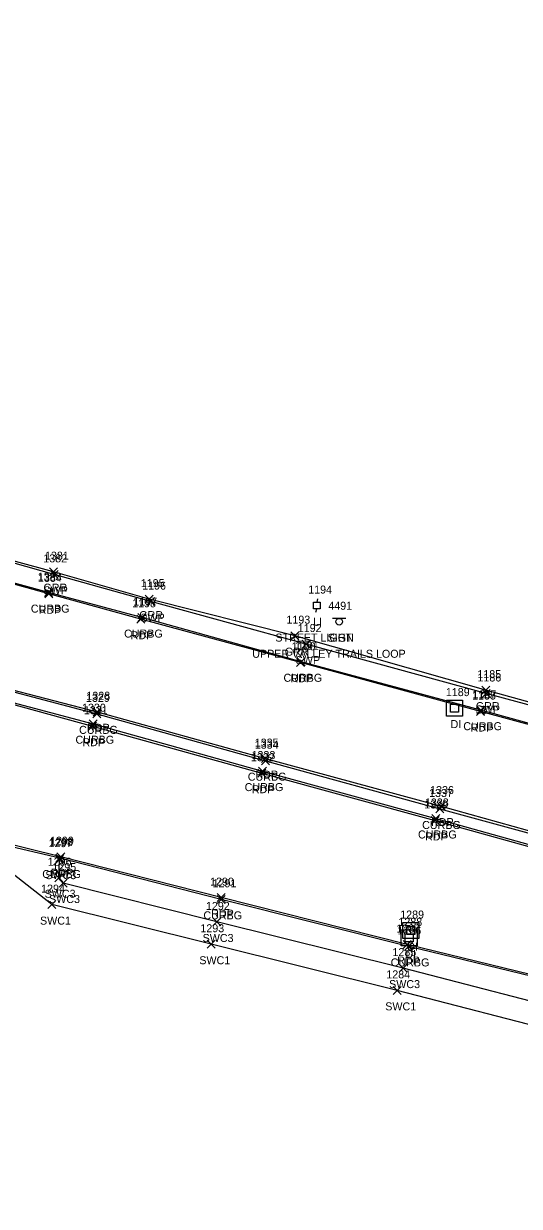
# Model space of a CAD drawing. Extents: x 1690689 to 1696275, y 438760 to 444007.
# Drawn here: x 1692829.1 to 1692953, y 438782.1 to 439077.7 of the extents above; entities that cross this region are included whole.
import ezdxf

# ---------------------------------------------------------------- set-up
doc = ezdxf.new("R2010")
doc.units = 0
for name, color, linetype in [('D_A', 7, 'Continuous'), ('D_I', 7, 'Continuous'), ('DS', 7, 'Continuous'), ('P_A', 7, 'Continuous'), ('P_I', 7, 'Continuous'), ('P_TIC', 7, 'Continuous'), ('PET', 7, 'Continuous'), ('R_A', 7, 'Continuous'), ('R_I', 7, 'Continuous'), ('R_TIC', 7, 'Continuous'), ('RC', 7, 'Continuous'), ('RGR', 7, 'Continuous'), ('RSW', 7, 'Continuous'), ('S_A', 7, 'Continuous'), ('S_C', 7, 'Continuous'), ('S_I', 7, 'Continuous'), ('SSGN', 7, 'Continuous'), ('U_A', 7, 'Continuous'), ('U_C', 7, 'Continuous'), ('U_I', 7, 'Continuous'), ('ULP', 7, 'Continuous')]:
    doc.layers.add(name, color=color, linetype=linetype)

msp = doc.modelspace()

# ---------------------------------------------------------------- linework, layer by layer
at = {"layer": 'DS'}
for p, q in [((1692934.77, 438908.65), (1692938.77, 438908.65)), ((1692934.77, 438904.65), (1692934.77, 438908.65)), ((1692935.77, 438905.65), (1692935.77, 438907.65)), ((1692935.77, 438907.65), (1692937.77, 438907.65)), ((1692937.77, 438907.65), (1692937.77, 438905.65)), ((1692938.77, 438908.65), (1692938.77, 438904.65)), ((1692937.77, 438905.65), (1692935.77, 438905.65)), ((1692936.77, 438906.65), (1692936.77, 438906.65)), ((1692936.77, 438906.65), (1692936.77, 438906.65)), ((1692938.77, 438904.65), (1692934.77, 438904.65)), ((1692923.93, 438853.06), (1692927.93, 438853.06)), ((1692923.93, 438849.06), (1692923.93, 438853.06)), ((1692924.93, 438850.06), (1692924.93, 438852.06)), ((1692924.93, 438852.06), (1692926.93, 438852.06)), ((1692926.93, 438852.06), (1692926.93, 438850.06)), ((1692927.93, 438853.06), (1692927.93, 438849.06)), ((1692923.47, 438851.22), (1692927.47, 438851.22)), ((1692923.47, 438847.22), (1692923.47, 438851.22)), ((1692927.93, 438849.06), (1692923.93, 438849.06)), ((1692924.47, 438848.22), (1692924.47, 438850.22)), ((1692924.47, 438850.22), (1692926.47, 438850.22)), ((1692926.93, 438850.06), (1692924.93, 438850.06)), ((1692925.47, 438849.22), (1692925.47, 438849.22)), ((1692925.47, 438849.22), (1692925.47, 438849.22)), ((1692925.94, 438851.06), (1692925.94, 438851.06)), ((1692925.94, 438851.06), (1692925.94, 438851.06)), ((1692926.47, 438850.22), (1692926.47, 438848.22)), ((1692927.47, 438851.22), (1692927.47, 438847.22)), ((1692927.47, 438847.22), (1692923.47, 438847.22)), ((1692926.47, 438848.22), (1692924.47, 438848.22))]:
    msp.add_line(p, q, dxfattribs=at)
at = {"layer": 'P_TIC'}
for points in [[(1692834.39, 438934.21), (1692836.39, 438936.21)], [(1692836.39, 438934.21), (1692834.39, 438936.21)], [(1692857.37, 438927.85), (1692859.37, 438929.85)], [(1692859.37, 438927.85), (1692857.37, 438929.85)], [(1692897.33, 438917.08), (1692899.33, 438919.08)], [(1692899.33, 438917.08), (1692897.33, 438919.08)], [(1692846.49, 438904.73), (1692848.49, 438906.73)], [(1692848.49, 438904.73), (1692846.49, 438906.73)], [(1692942.33, 438904.8), (1692944.33, 438906.8)], [(1692944.33, 438904.8), (1692942.33, 438906.8)], [(1692845.3, 438901.13), (1692847.3, 438903.13)], [(1692847.3, 438901.13), (1692845.3, 438903.13)], [(1692888.57, 438893.03), (1692890.57, 438895.03)], [(1692890.57, 438893.03), (1692888.57, 438895.03)], [(1692887.63, 438889.39), (1692889.63, 438891.39)], [(1692889.63, 438889.39), (1692887.63, 438891.39)], [(1692932.46, 438881.17), (1692934.46, 438883.17)], [(1692934.46, 438881.17), (1692932.46, 438883.17)], [(1692930.95, 438877.57), (1692932.95, 438879.57)], [(1692932.95, 438877.57), (1692930.95, 438879.57)], [(1692837.41, 438868.51), (1692839.41, 438870.51)], [(1692839.41, 438868.51), (1692837.41, 438870.51)], [(1692877.5, 438858.29), (1692879.5, 438860.29)], [(1692879.5, 438858.29), (1692877.5, 438860.29)], [(1692923.99, 438846.57), (1692925.99, 438848.57)], [(1692925.99, 438846.57), (1692923.99, 438848.57)]]:
    msp.add_lwpolyline(points, dxfattribs=at)
at = {"layer": 'PET'}
for points in [[(1693125.8, 439077.7), (1693116.74, 439032.37), (1693117.43, 439025.65), (1693115.9, 439015.71), (1693111.21, 439002.42), (1693106.01, 438991.1), (1693085.1, 438953.79), (1693072.88, 438932.02), (1693062.34, 438914.66), (1693048.8, 438898.45), (1693044.46, 438895.45), (1693034.2, 438890.8), (1693027.9, 438888.88), (1693020.98, 438887.4), (1693013.55, 438887.23), (1693007.21, 438888.24), (1692984.73, 438894.57), (1692943.33, 438905.8), (1692898.33, 438918.08), (1692858.37, 438928.85), (1692835.39, 438935.21), (1692797.06, 438945.81)], [(1693167.67, 438782.57), (1693141.53, 438790.2), (1693112.15, 438798.3), (1693087.86, 438805.04), (1693057.06, 438813.51), (1693019.12, 438823.55), (1692973.09, 438835.84), (1692924.99, 438847.57), (1692878.5, 438859.29), (1692838.41, 438869.51), (1692796.94, 438879.76), (1692752.35, 438890.07), (1692731.67, 438894.52), (1692658.1, 438910.21), (1692638.65, 438914.4), (1692605.27, 438921.45), (1692561.1, 438930.73), (1692527.61, 438937.28), (1692485.07, 438945.57), (1692435.03, 438955.4)], [(1692767.64, 438925.55), (1692788.12, 438920.87), (1692810.81, 438915.2), (1692847.49, 438905.73), (1692889.57, 438894.03), (1692933.46, 438882.17), (1692980.03, 438869.15), (1693015.23, 438859.21), (1693027.67, 438855.11), (1693029.13, 438853.87), (1693029.26, 438853.13)], [(1692765.95, 438921.86), (1692787.57, 438917.51), (1692810.13, 438912.04), (1692846.3, 438902.13), (1692888.63, 438890.39), (1692931.95, 438878.57), (1692979.05, 438865.49), (1693014.1, 438855.52), (1693026.61, 438851.49), (1693027.81, 438851.47), (1693028.79, 438852.15), (1693029.26, 438853.13)]]:
    msp.add_lwpolyline(points, dxfattribs=at)
at = {"layer": 'R_TIC'}
for points in [[(1692835.58, 438939.74), (1692837.58, 438941.74)], [(1692837.58, 438939.74), (1692835.58, 438941.74)], [(1692835.71, 438939.07), (1692837.71, 438941.07)], [(1692837.71, 438939.07), (1692835.71, 438941.07)], [(1692834.33, 438934.51), (1692836.33, 438936.51)], [(1692836.33, 438934.51), (1692834.33, 438936.51)], [(1692859.53, 438932.88), (1692861.53, 438934.88)], [(1692861.53, 438932.88), (1692859.53, 438934.88)], [(1692859.92, 438932.26), (1692861.92, 438934.26)], [(1692861.92, 438932.26), (1692859.92, 438934.26)], [(1692857.65, 438928.27), (1692859.65, 438930.27)], [(1692859.65, 438928.27), (1692857.65, 438930.27)], [(1692895.92, 438923.75), (1692897.92, 438925.75)], [(1692897.92, 438923.75), (1692895.92, 438925.75)], [(1692898.76, 438921.66), (1692900.76, 438923.66)], [(1692900.76, 438921.66), (1692898.76, 438923.66)], [(1692897.49, 438917.23), (1692899.49, 438919.23)], [(1692899.49, 438917.23), (1692897.49, 438919.23)], [(1692943.65, 438910.14), (1692945.65, 438912.14)], [(1692945.65, 438910.14), (1692943.65, 438912.14)], [(1692943.72, 438909.3), (1692945.72, 438911.3)], [(1692945.72, 438909.3), (1692943.72, 438911.3)], [(1692846.4, 438904.21), (1692848.4, 438906.21)], [(1692848.4, 438904.21), (1692846.4, 438906.21)], [(1692942.42, 438905.13), (1692944.42, 438907.13)], [(1692944.42, 438905.13), (1692942.42, 438907.13)], [(1692845.5, 438901.75), (1692847.5, 438903.75)], [(1692847.5, 438901.75), (1692845.5, 438903.75)], [(1692888.57, 438892.51), (1692890.57, 438894.51)], [(1692890.57, 438892.51), (1692888.57, 438894.51)], [(1692887.78, 438889.91), (1692889.78, 438891.91)], [(1692889.78, 438889.91), (1692887.78, 438891.91)], [(1692932.14, 438880.44), (1692934.14, 438882.44)], [(1692934.14, 438880.44), (1692932.14, 438882.44)], [(1692931.11, 438878.07), (1692933.11, 438880.07)], [(1692933.11, 438878.07), (1692931.11, 438880.07)], [(1692837.06, 438867.91), (1692839.06, 438869.91)], [(1692839.06, 438867.91), (1692837.06, 438869.91)], [(1692837.19, 438868.18), (1692839.19, 438870.18)], [(1692839.19, 438868.18), (1692837.19, 438870.18)], [(1692836.89, 438863.26), (1692838.89, 438865.26)], [(1692838.89, 438863.26), (1692836.89, 438865.26)], [(1692838, 438861.94), (1692840, 438863.94)], [(1692840, 438861.94), (1692838, 438863.94)], [(1692835.17, 438856.54), (1692837.17, 438858.54)], [(1692837.17, 438856.54), (1692835.17, 438858.54)], [(1692877.46, 438857.86), (1692879.46, 438859.86)], [(1692879.46, 438857.86), (1692877.46, 438859.86)], [(1692876.37, 438852.2), (1692878.37, 438854.2)], [(1692878.37, 438852.2), (1692876.37, 438854.2)], [(1692874.99, 438846.64), (1692876.99, 438848.64)], [(1692876.99, 438846.64), (1692874.99, 438848.64)], [(1692924.29, 438846.1), (1692926.29, 438848.1)], [(1692926.29, 438846.1), (1692924.29, 438848.1)], [(1692922.99, 438840.68), (1692924.99, 438842.68)], [(1692924.99, 438840.68), (1692922.99, 438842.68)], [(1692921.46, 438835.11), (1692923.46, 438837.11)], [(1692923.46, 438835.11), (1692921.46, 438837.11)]]:
    msp.add_lwpolyline(points, dxfattribs=at)
at = {"layer": 'RC'}
for points in [[(1693007.26, 438888.54), (1692984.87, 438894.72), (1692943.42, 438906.13), (1692898.49, 438918.23), (1692858.65, 438929.27), (1692835.33, 438935.51), (1692797.49, 438945.86), (1692745.37, 438957.23), (1692684.06, 438970.13), (1692664.88, 438974.8), (1692632.07, 438981.54), (1692605.04, 438987.41), (1692554.61, 438997.65), (1692506.45, 439007.89), (1692458.66, 439018.07), (1692409.83, 439028.32)], [(1693167.44, 438782.14), (1693141.42, 438789.93), (1693119.24, 438796.02), (1693112.17, 438798), (1693087.95, 438804.88), (1693056.95, 438813.29), (1693019.1, 438823.35), (1692973.04, 438835.52), (1692925.29, 438847.1), (1692878.46, 438858.86), (1692838.19, 438869.18), (1692796.47, 438878.9), (1692752.32, 438889.87), (1692731.59, 438894.27), (1692657.89, 438909.92), (1692639.33, 438913.93), (1692605.34, 438921.22), (1692561.27, 438930.49), (1692527.54, 438937.1), (1692485.06, 438945.4), (1692435.02, 438955.15)], [(1692766.36, 438922.45), (1692787.63, 438917.87), (1692810.3, 438912.33), (1692846.5, 438902.75), (1692888.78, 438890.91), (1692932.11, 438879.07), (1692979.27, 438865.93), (1693014.3, 438855.98), (1693026.63, 438852.11), (1693027.78, 438852.01)], [(1692767.42, 438924.95), (1692788.17, 438920.39), (1692810.74, 438914.88), (1692847.4, 438905.21), (1692889.57, 438893.51), (1692933.14, 438881.44), (1692979.89, 438868.71), (1693015.06, 438858.69), (1693027.38, 438854.59), (1693028.5, 438853.53), (1693028.46, 438852.76), (1693027.78, 438852.01)]]:
    msp.add_lwpolyline(points, dxfattribs=at)
at = {"layer": 'RGR'}
msp.add_lwpolyline([(1693073.53, 438952.26), (1693072, 438944.32), (1693067.94, 438934.93), (1693057.5, 438916.87), (1693045.6, 438902.71), (1693040.89, 438899.43), (1693031.63, 438895.36), (1693017.18, 438892.86), (1693013.23, 438892.96), (1693006.72, 438894.11), (1692986.35, 438899.55), (1692944.65, 438911.14), (1692896.92, 438924.75), (1692860.53, 438933.88), (1692836.58, 438940.74), (1692798.54, 438951.07), (1692780.52, 438955.46)], dxfattribs=at)
at = {"layer": 'RSW'}
for points in [[(1693008.71, 438893.22), (1692986.15, 438899.12), (1692944.72, 438910.3), (1692899.76, 438922.66), (1692860.92, 438933.26), (1692836.71, 438940.07), (1692798.61, 438950.76), (1692797.49, 438945.86)], [(1692961.7, 438815.71), (1692965.05, 438825.1), (1692922.46, 438836.11), (1692875.99, 438847.64), (1692836.17, 438857.54), (1692822.55, 438868.12), (1692796.53, 438874.61), (1692766.39, 438881.99), (1692766.23, 438881.85), (1692750.5, 438885.32), (1692729.84, 438889.75), (1692656.64, 438905.41), (1692656.72, 438906.14), (1692638.39, 438910.1), (1692639.33, 438913.93)], [(1693087.68, 438804.2), (1693086.09, 438802.9), (1693083.8, 438801.45), (1693080.94, 438801.34), (1693063.4, 438806.38), (1693024.27, 438816.89), (1692997.77, 438823.45), (1692971.56, 438829.3), (1692923.99, 438841.68), (1692877.37, 438853.2), (1692839, 438862.94), (1692837.89, 438864.26), (1692838.06, 438868.91)]]:
    msp.add_lwpolyline(points, dxfattribs=at)
at = {"layer": 'SSGN'}
for p, q in [((1692906.33, 438929.09), (1692909.66, 438929.09)), ((1692907.98, 438928.25), (1692907.98, 438928.25))]:
    msp.add_line(p, q, dxfattribs=at)
msp.add_circle((1692907.98, 438928.25), 0.833, dxfattribs=at)
at = {"layer": 'ULP'}
for p, q in [((1692901.53, 438931.44), (1692901.53, 438933.1)), ((1692901.53, 438933.1), (1692903.2, 438933.1)), ((1692903.2, 438931.44), (1692901.53, 438931.44)), ((1692902.12, 438930.6), (1692902.37, 438931.44)), ((1692902.53, 438933.94), (1692902.37, 438933.1)), ((1692902.37, 438932.27), (1692902.37, 438932.27)), ((1692903.2, 438933.1), (1692903.2, 438931.44))]:
    msp.add_line(p, q, dxfattribs=at)

# ---------------------------------------------------------------- texts
at = {"layer": 'D_A'}
for p in [(1692935.83, 438901.65), (1692924.53, 438844.22), (1692924.99, 438846.06)]:
    msp.add_text('DI', height=2, dxfattribs=at).set_placement(p)
at = {"layer": 'D_I'}
for s, p in [('1189', (1692934.64, 438909.65)), ('1289', (1692923.24, 438854.06)), ('1288', (1692922.78, 438852.22))]:
    msp.add_text(s, height=2, dxfattribs=at).set_placement(p)
at = {"layer": 'P_A'}
for p in [(1692832.88, 438930.21), (1692855.85, 438923.85), (1692895.81, 438913.08), (1692844.98, 438900.73), (1692940.82, 438900.8), (1692843.79, 438897.13), (1692887.06, 438889.03), (1692886.12, 438885.39), (1692930.95, 438877.17), (1692929.44, 438873.57), (1692835.9, 438864.51), (1692875.99, 438854.29), (1692922.48, 438842.57)]:
    msp.add_text('RDP', height=2, dxfattribs=at).set_placement(p)
at = {"layer": 'P_I'}
for s, p in [('1384', (1692832.7, 438938.21)), ('1198', (1692856.24, 438931.85)), ('1190', (1692896.11, 438921.08)), ('1328', (1692844.79, 438908.73)), ('1188', (1692941.2, 438908.8)), ('1331', (1692844.17, 438905.13)), ('1335', (1692886.88, 438897.03)), ('1332', (1692885.94, 438893.39)), ('1336', (1692930.71, 438885.17)), ('1339', (1692929.25, 438881.57)), ('1299', (1692835.71, 438872.51)), ('1290', (1692875.72, 438862.29)), ('1287', (1692922.3, 438850.57))]:
    msp.add_text(s, height=2, dxfattribs=at).set_placement(p)
at = {"layer": 'R_A'}
for s, p in [('GRR', (1692834.07, 438935.74)), ('SWP', (1692834.07, 438935.07)), ('CURBG', (1692830.92, 438930.51)), ('GRR', (1692858.02, 438928.88)), ('SWP', (1692858.29, 438928.26)), ('CURBG', (1692854.23, 438924.27)), ('GRR', (1692894.41, 438919.75)), ('SWP', (1692897.12, 438917.66)), ('CURBG', (1692894.07, 438913.23)), ('GRR', (1692942.14, 438906.14)), ('SWP', (1692942.08, 438905.3)), ('CURBG', (1692842.98, 438900.21)), ('CURBG', (1692939, 438901.13)), ('CURBG', (1692842.08, 438897.75)), ('CURBG', (1692885.15, 438888.51)), ('CURBG', (1692884.36, 438885.91)), ('CURBG', (1692928.72, 438876.44)), ('CURBG', (1692927.69, 438874.07)), ('CURBG', (1692833.77, 438864.18)), ('SWC3', (1692834.54, 438863.91)), ('SWC3', (1692834.36, 438859.26)), ('SWC3', (1692835.47, 438857.94)), ('SWC1', (1692833.21, 438852.54)), ('CURBG', (1692874.05, 438853.86)), ('SWC3', (1692873.85, 438848.2)), ('SWC1', (1692873.03, 438842.64)), ('CURBG', (1692920.87, 438842.1)), ('SWC3', (1692920.46, 438836.68)), ('SWC1', (1692919.5, 438831.11))]:
    msp.add_text(s, height=2, dxfattribs=at).set_placement(p)
at = {"layer": 'R_I'}
for s, p in [('1382', (1692834.02, 438943.07)), ('1381', (1692834.45, 438943.74)), ('1383', (1692832.64, 438938.51)), ('1195', (1692858.4, 438936.88)), ('1196', (1692858.74, 438936.26)), ('1197', (1692856.52, 438932.27)), ('1193', (1692894.8, 438927.75)), ('1192', (1692897.63, 438925.66)), ('1191', (1692896.93, 438921.23)), ('1185', (1692942.52, 438914.14)), ('1186', (1692942.54, 438913.3)), ('1187', (1692941.29, 438909.13)), ('1330', (1692843.72, 438905.75)), ('1329', (1692844.7, 438908.21)), ('1333', (1692886.08, 438893.91)), ('1334', (1692886.88, 438896.51)), ('1338', (1692929.41, 438882.07)), ('1337', (1692930.45, 438884.44)), ('1297', (1692835.37, 438871.91)), ('1298', (1692835.5, 438872.18)), ('1296', (1692835.14, 438867.26)), ('1295', (1692836.3, 438865.94)), ('1291', (1692876.34, 438861.86)), ('1294', (1692833.48, 438860.54)), ('1292', (1692874.68, 438856.2)), ('1293', (1692873.29, 438850.64)), ('1286', (1692922.54, 438850.1)), ('1285', (1692921.3, 438844.68)), ('1284', (1692919.76, 438839.11))]:
    msp.add_text(s, height=2, dxfattribs=at).set_placement(p)
at = {"layer": 'S_A'}
msp.add_text('SIGN', height=2, dxfattribs=at).set_placement((1692905.11, 438923.23))
at = {"layer": 'S_C'}
msp.add_text('UPPER VALLEY TRAILS LOOP', height=2, dxfattribs=at).set_placement((1692886.26, 438919.23))
at = {"layer": 'S_I'}
msp.add_text('4491', height=2, dxfattribs=at).set_placement((1692905.26, 438931.23))
at = {"layer": 'U_A'}
msp.add_text('LI', height=2, dxfattribs=at).set_placement((1692901.47, 438927.27))
at = {"layer": 'U_C'}
msp.add_text('STREET LIGHT', height=2, dxfattribs=at).set_placement((1692892.03, 438923.27))
at = {"layer": 'U_I'}
msp.add_text('1194', height=2, dxfattribs=at).set_placement((1692900.24, 438935.27))

doc.saveas('drawing.dxf')
